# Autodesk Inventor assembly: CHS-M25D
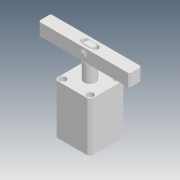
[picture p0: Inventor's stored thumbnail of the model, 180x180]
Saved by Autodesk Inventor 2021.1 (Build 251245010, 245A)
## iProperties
Created: 2019-05
Part Number: CHS-M25D
Description: STEP AP203
Document SubType Name: Assembly
Designer: user
Title: chs-m25d_asm.STEP
Revision Number: ÈÎºÎ
Sending System: SolidWorks 2017
Preprocessor: SwSTEP 2.0
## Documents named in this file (6)
- D:\Vault_2016\Projekty\Clamptek\Hydraulic\CHS\CHS-25\Inventor\CHS-M25D\CHS-M25D.iam
- D:\Vault_2016\Projekty\Clamptek\Hydraulic\CHS\CHS-25\Inventor\CHS-M25D\CHS-M25-03.ipt
- D:\Vault_2016\Projekty\Clamptek\Hydraulic\CHS\CHS-25\Inventor\CHS-M25D\CHS-25D-02_6_1.ipt
- D:\Vault_2016\Projekty\Clamptek\Hydraulic\CHS\CHS-25\Inventor\CHS-M25D\CHS-25D-01_6.ipt
- D:\Vault_2016\Projekty\Clamptek\Hydraulic\CHS\CHS-25\Inventor\CHS-M25D\Xiao.ipt
- D:\Vault_2016\Projekty\Clamptek\Hydraulic\CHS\CHS-25\Inventor\CHS-M25D\Öá8µ²È¦.ipt
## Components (6 placed, 6 different names)
1. CHS-M25-03_1
2. CHS-25D-02_6_1_2
3. CHS-25D-01_6_3
4. Xiao_4
5. Öá8µ²È¦_5
6. Öá8µ²È¦_6
